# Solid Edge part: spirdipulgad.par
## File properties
Username: Kasutaja
Author: Kasutaja
Template: Iso Metric Part.par
Last saved by: Kasutaja
Revision: 4
Application: Solid Edge
Accuracy: 0,990
Face Style: Model Default
Fill Style: Normal
Coef. of Thermal Exp: 0.0
Thermal Conductivity: 0.0
Specific Heat: 0.0
Modulus of Elasticity: 0.0
Poisson's Ratio: 0.0
Yield Stress: 0.0
Ultimate Stress: 0.0
Elongation: 0.0
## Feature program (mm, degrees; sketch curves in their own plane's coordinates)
sketch for "unnamed Protrusion 1" plane through (0, 0, 0) normal (1, 0, 0) x-axis (0, 1, 0)
  circle centre (29.6279, 0) radius 2.5
extrude "unnamed Protrusion 1" add finite 300 symmetric
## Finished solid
Body 1: solid body, 3 faces, 2 edges, 0 vertices.
  Faces by surface: plane 2, cylinder 1
  Edges by curve: circle 2
Bounding box of the edges (mm): 300.000 x 5.000 x 5.000, from (-150, 27.1279, -2.5) to (150, 32.1279, 2.5).
Cylindrical faces by radius (mm): R2.5 x1
Planar faces by outward normal: +x 1, -x 1
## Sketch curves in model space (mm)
circle centre (0, 29.6279, 0) radius 2.5
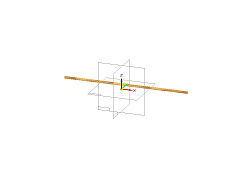
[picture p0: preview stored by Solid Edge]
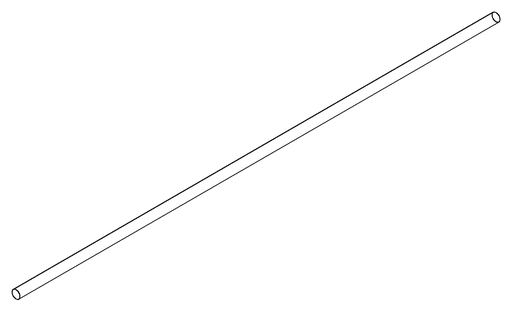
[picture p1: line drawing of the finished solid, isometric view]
